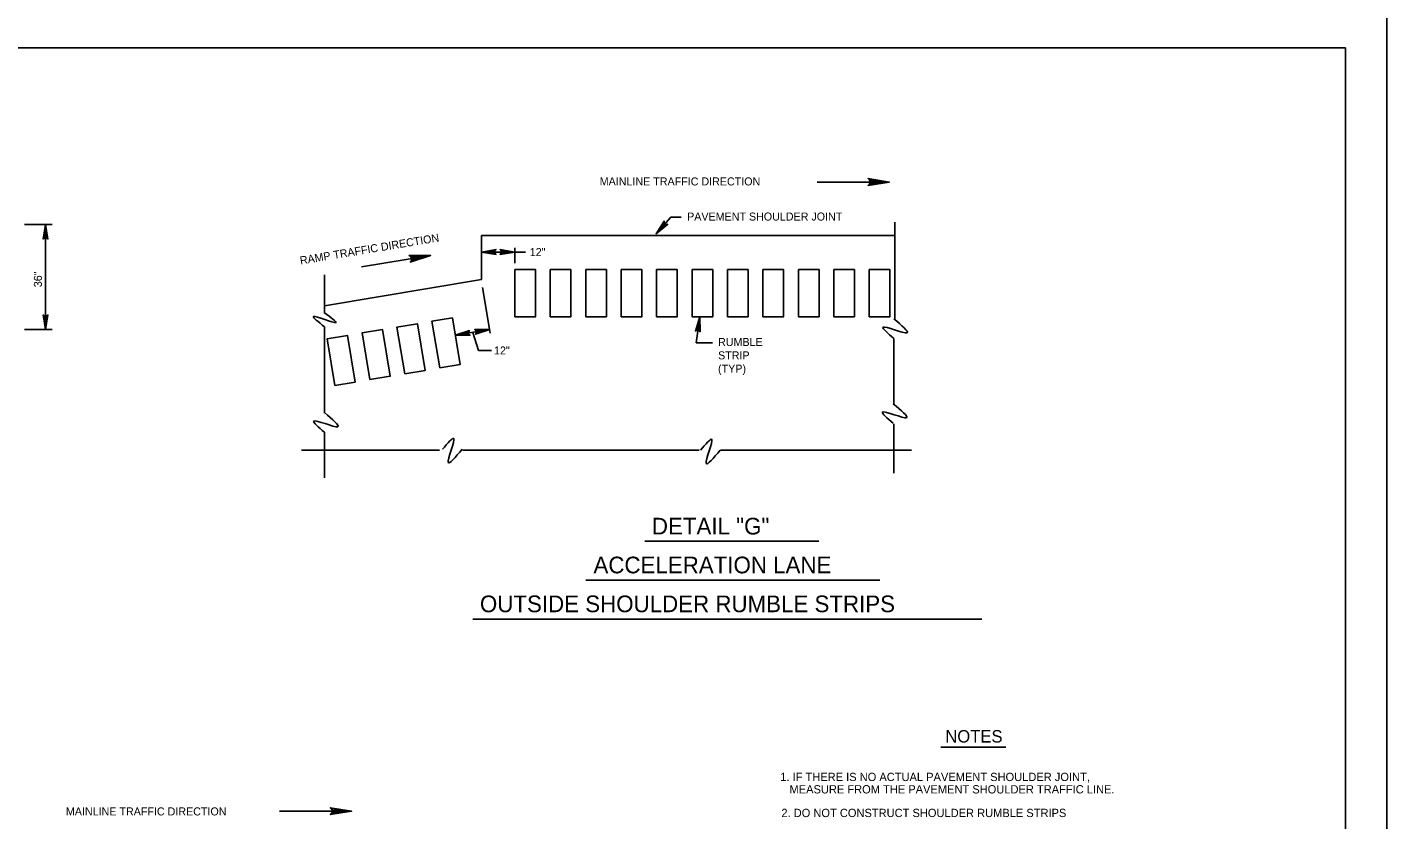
# Model space of a CAD drawing. Extents: x 632008 to 634206, y 294231 to 297795.
# Drawn here: x 632356.5 to 632848.9, y 295124 to 295411.1 of the extents above; entities that cross this region are included whole.
import ezdxf

# ---------------------------------------------------------------- set-up
doc = ezdxf.new("R2010")
doc.units = 0
for name, color, linetype in [('1', 7, 'Continuous'), ('2', 7, 'Continuous'), ('3', 7, 'Continuous'), ('PLT-BNDY', 7, 'Continuous')]:
    doc.layers.add(name, color=color, linetype=linetype)

msp = doc.modelspace()

# ---------------------------------------------------------------- linework, layer by layer
at = {"layer": '1'}
for p, q in [((632642.58, 295355.01), (632668.68, 295355.01)), ((632365.52, 295339.67), (632355.54, 295339.67)), ((632363.13, 295301.54), (632363.13, 295339.67)), ((632670.67, 295305.1), (632670.67, 295340.5)), ((632520.96, 295319.71), (632520.96, 295335.67)), ((632520.96, 295335.67), (632670.67, 295335.67)), ((632477.53, 295324.28), (632502.55, 295328.46)), ((632536.9, 295329.67), (632520.96, 295329.67)), ((632533.1, 295325.63), (632533.1, 295331.19)), ((632464.12, 295307.54), (632464.12, 295321.4)), ((632464.12, 295310.22), (632520.96, 295319.71)), ((632521.43, 295316.86), (632524.2, 295300.26)), ((632464.12, 295271.27), (632464.12, 295302.62)), ((632600.04, 295306.19), (632598.79, 295296.71)), ((632365.52, 295301.54), (632355.54, 295301.54)), ((632511.5, 295299.49), (632523.98, 295301.58)), ((632517.81, 295300.55), (632519.95, 295293.97)), ((632670.29, 295274.72), (632670.29, 295298.35)), ((632524.62, 295293.97), (632519.95, 295293.97)), ((632604.64, 295296.71), (632598.79, 295296.71)), ((632464.12, 295247.9), (632464.12, 295264.34)), ((632670.32, 295249.58), (632670.32, 295267.4)), ((632505.81, 295257.92), (632455.8, 295257.92)), ((632599.89, 295257.92), (632514.19, 295257.92)), ((632676.73, 295257.92), (632607.62, 295257.92)), ((632580.17, 295224.86), (632643.13, 295224.86)), ((632558.8, 295210.73), (632665.32, 295210.73)), ((632517.82, 295196.61), (632702.24, 295196.61)), ((632447.85, 295127.09), (632473.94, 295127.09))]:
    msp.add_line(p, q, dxfattribs=at)
for points in [[(632833.86, 294839.62), (632833.86, 295403.62), (632047.86, 295403.62), (632047.86, 294839.62), (632833.86, 294839.62), (632833.86, 294865.98), (632633.86, 294865.98), (632633.86, 294930.66), (632833.86, 294930.66), (632833.86, 294959.62), (632633.86, 294959.62), (632633.86, 294839.62), (632712.66, 294839.62), (632712.66, 294865.98), (632712.66, 294839.62), (632789.66, 294839.62), (632789.66, 294865.98), (632789.66, 294853.66), (632833.86, 294853.66)], [(632833.86, 294839.62), (632833.86, 295403.62), (632047.86, 295403.62), (632047.86, 294839.62), (632833.86, 294839.62), (632833.86, 294865.98), (632633.86, 294865.98), (632633.86, 294930.66), (632833.86, 294930.66), (632833.86, 294959.62), (632633.86, 294959.62), (632633.86, 294839.62), (632712.66, 294839.62), (632712.66, 294865.98), (632712.66, 294839.62), (632789.66, 294839.62), (632789.66, 294865.98), (632789.66, 294853.66), (632833.86, 294853.66)], [(632833.86, 294839.62), (632833.86, 295403.62), (632047.86, 295403.62), (632047.86, 294839.62), (632833.86, 294839.62), (632833.86, 294865.98), (632633.86, 294865.98), (632633.86, 294930.66), (632833.86, 294930.66), (632833.86, 294959.62), (632633.86, 294959.62), (632633.86, 294839.62), (632712.66, 294839.62), (632712.66, 294865.98), (632712.66, 294839.62), (632789.66, 294839.62), (632789.66, 294865.98), (632789.66, 294853.66), (632833.86, 294853.66)], [(632833.86, 294839.62), (632833.86, 295403.62), (632047.86, 295403.62), (632047.86, 294839.62), (632833.86, 294839.62), (632833.86, 294865.98), (632633.86, 294865.98), (632633.86, 294930.66), (632833.86, 294930.66), (632833.86, 294959.62), (632633.86, 294959.62), (632633.86, 294839.62), (632712.66, 294839.62), (632712.66, 294865.98), (632712.66, 294839.62), (632789.66, 294839.62), (632789.66, 294865.98), (632789.66, 294853.66), (632833.86, 294853.66)], [(632833.86, 294839.62), (632833.86, 295403.62), (632047.86, 295403.62), (632047.86, 294839.62), (632833.86, 294839.62), (632833.86, 294865.98), (632633.86, 294865.98), (632633.86, 294930.66), (632833.86, 294930.66), (632833.86, 294959.62), (632633.86, 294959.62), (632633.86, 294839.62), (632712.66, 294839.62), (632712.66, 294865.98), (632712.66, 294839.62), (632789.66, 294839.62), (632789.66, 294865.98), (632789.66, 294853.66), (632833.86, 294853.66)], [(632833.86, 294839.62), (632833.86, 295403.62), (632047.86, 295403.62), (632047.86, 294839.62), (632833.86, 294839.62), (632833.86, 294865.98), (632633.86, 294865.98), (632633.86, 294930.66), (632833.86, 294930.66), (632833.86, 294959.62), (632633.86, 294959.62), (632633.86, 294839.62), (632712.66, 294839.62), (632712.66, 294865.98), (632712.66, 294839.62), (632789.66, 294839.62), (632789.66, 294865.98), (632789.66, 294853.66), (632833.86, 294853.66)], [(632661.37, 295355.93), (632661.64, 295355.4), (632668.68, 295355.01), (632661.37, 295355.93), (632660.99, 295356.25), (632668.68, 295355.01), (632661.65, 295354.66), (632661.39, 295354.14), (632668.68, 295355.01), (632660.99, 295353.79), (632661.39, 295354.14)], [(632584.26, 295336.31), (632589.52, 295342.27), (632593.26, 295342.27)], [(632362.5, 295334.59), (632362.87, 295334.78), (632363.13, 295339.67), (632362.5, 295334.59), (632362.28, 295334.33), (632363.13, 295339.67), (632363.38, 295334.79), (632363.74, 295334.61), (632363.13, 295339.67), (632363.98, 295334.33), (632363.74, 295334.61)], [(632588.1, 295339.69), (632587.7, 295339.8), (632584.26, 295336.31), (632588.1, 295339.69), (632588.44, 295339.74), (632584.26, 295336.31), (632587.31, 295340.13), (632587.16, 295340.5), (632584.26, 295336.31), (632587.16, 295340.87), (632587.16, 295340.5)], [(632495.19, 295328.16), (632495.55, 295327.68), (632502.55, 295328.46), (632495.19, 295328.16), (632494.77, 295328.41), (632502.55, 295328.46), (632495.68, 295326.96), (632495.51, 295326.4), (632502.55, 295328.46), (632495.18, 295325.99), (632495.51, 295326.4)], [(632526.03, 295329.03), (632525.84, 295329.4), (632520.96, 295329.67), (632526.03, 295329.03), (632526.29, 295328.81), (632520.96, 295329.67), (632525.84, 295329.91), (632526.01, 295330.28), (632520.96, 295329.67), (632526.29, 295330.52), (632526.01, 295330.28)], [(632528.02, 295330.31), (632528.21, 295329.94), (632533.1, 295329.67), (632528.02, 295330.31), (632527.76, 295330.53), (632533.1, 295329.67), (632528.22, 295329.43), (632528.04, 295329.07), (632533.1, 295329.67), (632527.76, 295328.82), (632528.04, 295329.07)], [(632533.1, 295323.3), (632540.58, 295323.3), (632540.58, 295306.19), (632533.1, 295306.19), (632533.1, 295323.3)], [(632545.93, 295323.3), (632553.42, 295323.3), (632553.42, 295306.19), (632545.93, 295306.19), (632545.93, 295323.3)], [(632558.76, 295323.3), (632566.25, 295323.3), (632566.25, 295306.19), (632558.76, 295306.19), (632558.76, 295323.3)], [(632571.6, 295323.3), (632579.08, 295323.3), (632579.08, 295306.19), (632571.6, 295306.19), (632571.6, 295323.3)], [(632584.43, 295323.3), (632591.92, 295323.3), (632591.92, 295306.19), (632584.43, 295306.19), (632584.43, 295323.3)], [(632597.26, 295323.3), (632604.75, 295323.3), (632604.75, 295306.19), (632597.26, 295306.19), (632597.26, 295323.3)], [(632610.1, 295323.3), (632617.58, 295323.3), (632617.58, 295306.19), (632610.1, 295306.19), (632610.1, 295323.3)], [(632622.93, 295323.3), (632630.42, 295323.3), (632630.42, 295306.19), (632622.93, 295306.19), (632622.93, 295323.3)], [(632635.77, 295323.3), (632643.25, 295323.3), (632643.25, 295306.19), (632635.77, 295306.19), (632635.77, 295323.3)], [(632648.6, 295323.3), (632656.08, 295323.3), (632656.08, 295306.19), (632648.6, 295306.19), (632648.6, 295323.3)], [(632661.43, 295323.3), (632668.92, 295323.3), (632668.92, 295306.19), (632661.43, 295306.19), (632661.43, 295323.3)], [(632363.77, 295306.61), (632363.4, 295306.42), (632363.13, 295301.54), (632363.77, 295306.61), (632363.99, 295306.87), (632363.13, 295301.54), (632362.89, 295306.42), (632362.53, 295306.6), (632363.13, 295301.54), (632362.29, 295306.87), (632362.53, 295306.6)], [(632493.22, 295285.57), (632500.61, 295286.8), (632497.79, 295303.68), (632490.4, 295302.44), (632493.22, 295285.57)], [(632505.88, 295287.68), (632513.26, 295288.91), (632510.45, 295305.79), (632503.06, 295304.56), (632505.88, 295287.68)], [(632598.74, 295301.24), (632599.13, 295301.38), (632600.04, 295306.19), (632598.74, 295301.24), (632598.49, 295301.01), (632600.04, 295306.19), (632599.64, 295301.31), (632599.98, 295301.09), (632600.04, 295306.19), (632600.18, 295300.79), (632599.98, 295301.09)], [(632467.91, 295281.34), (632475.29, 295282.57), (632472.47, 295299.45), (632465.09, 295298.21), (632467.91, 295281.34)], [(632480.57, 295283.45), (632487.95, 295284.68), (632485.13, 295301.56), (632477.75, 295300.33), (632480.57, 295283.45)], [(632516.61, 295299.7), (632516.36, 295300.03), (632511.5, 295299.49), (632516.61, 295299.7), (632516.9, 295299.52), (632511.5, 295299.49), (632516.27, 295300.54), (632516.39, 295300.92), (632511.5, 295299.49), (632516.62, 295301.21), (632516.39, 295300.92)], [(632518.87, 295301.37), (632519.12, 295301.04), (632523.98, 295301.58), (632518.87, 295301.37), (632518.58, 295301.55), (632523.98, 295301.58), (632519.21, 295300.54), (632519.09, 295300.15), (632523.98, 295301.58), (632518.86, 295299.86), (632519.09, 295300.15)], [(632466.64, 295128.01), (632466.91, 295127.48), (632473.94, 295127.09), (632466.64, 295128.01), (632466.26, 295128.33), (632473.94, 295127.09), (632466.91, 295126.74), (632466.66, 295126.22), (632473.94, 295127.09), (632466.26, 295125.87), (632466.66, 295126.22)]]:
    msp.add_lwpolyline(points, dxfattribs=at)
for points in [[(632464.17, 295302.57), (632460.18, 295306.33), (632468.28, 295304.09), (632464.17, 295307.62)], [(632670.32, 295298.36), (632666.41, 295302.42), (632675.11, 295300.39), (632670.32, 295305.47)], [(632670.13, 295267.61), (632666.22, 295271.67), (632674.91, 295269.64), (632670.13, 295274.72)], [(632464.15, 295264.36), (632460.24, 295268.42), (632468.94, 295266.39), (632464.15, 295271.47)], [(632506.9, 295258.19), (632510.96, 295262.11), (632508.93, 295253.41), (632514.01, 295258.19)], [(632600.33, 295257.87), (632604.4, 295261.79), (632602.37, 295253.09), (632607.44, 295257.87)]]:
    msp.add_spline(points, degree=3, dxfattribs=at)
at = {"layer": '2'}
msp.add_line((632687.35, 295150.28), (632710.91, 295150.28), dxfattribs=at)
at = {"layer": 'PLT-BNDY'}
msp.add_lwpolyline([(632007.86, 295418.62), (632848.86, 295418.62), (632848.86, 294824.62), (632007.86, 294824.62)], close=True, dxfattribs=at)

# ---------------------------------------------------------------- texts
at = {"layer": '1'}
for s, height, p in [('MAINLINE TRAFFIC DIRECTION', 2.8989, (632563.82, 295353.79)), ('PAVEMENT SHOULDER JOINT', 2.898, (632595.47, 295341.07)), ('12"', 2.899, (632538.48, 295328.21)), ('RUMBLE', 2.899, (632606.68, 295295.61)), ('12"', 2.899, (632525.54, 295292.54)), ('STRIP', 2.899, (632606.68, 295290.78)), ('(TYP)', 2.899, (632606.68, 295285.96)), ('DETAIL "G"', 6.039, (632582.72, 295227.33)), ('ACCELERATION LANE', 6.0395, (632561.56, 295213.26)), ('OUTSIDE SHOULDER RUMBLE STRIPS', 6.0395, (632520.44, 295199.18)), ('MAINLINE TRAFFIC DIRECTION', 2.8989, (632370.51, 295125.55))]:
    msp.add_text(s, height=height, dxfattribs=at).set_placement(p)
for s, height, rotation, p in [('RAMP TRAFFIC DIRECTION', 2.8989, 9.482, (632455.5, 295325.11)), ('36"', 2.899, 90, (632361.81, 295316.92))]:
    msp.add_text(s, height=height, rotation=rotation, dxfattribs=at).set_placement(p)
at = {"layer": '3'}
for s, height, p in [('NOTES', 4.5, (632688.97, 295151.96)), ('1. IF THERE IS NO ACTUAL PAVEMENT SHOULDER JOINT,', 3, (632629.21, 295138)), ('   MEASURE FROM THE PAVEMENT SHOULDER TRAFFIC LINE.', 3, (632629.21, 295133.51)), ('2. DO NOT CONSTRUCT SHOULDER RUMBLE STRIPS', 3, (632629.61, 295124.95))]:
    msp.add_text(s, height=height, dxfattribs=at).set_placement(p)

doc.saveas('drawing.dxf')
